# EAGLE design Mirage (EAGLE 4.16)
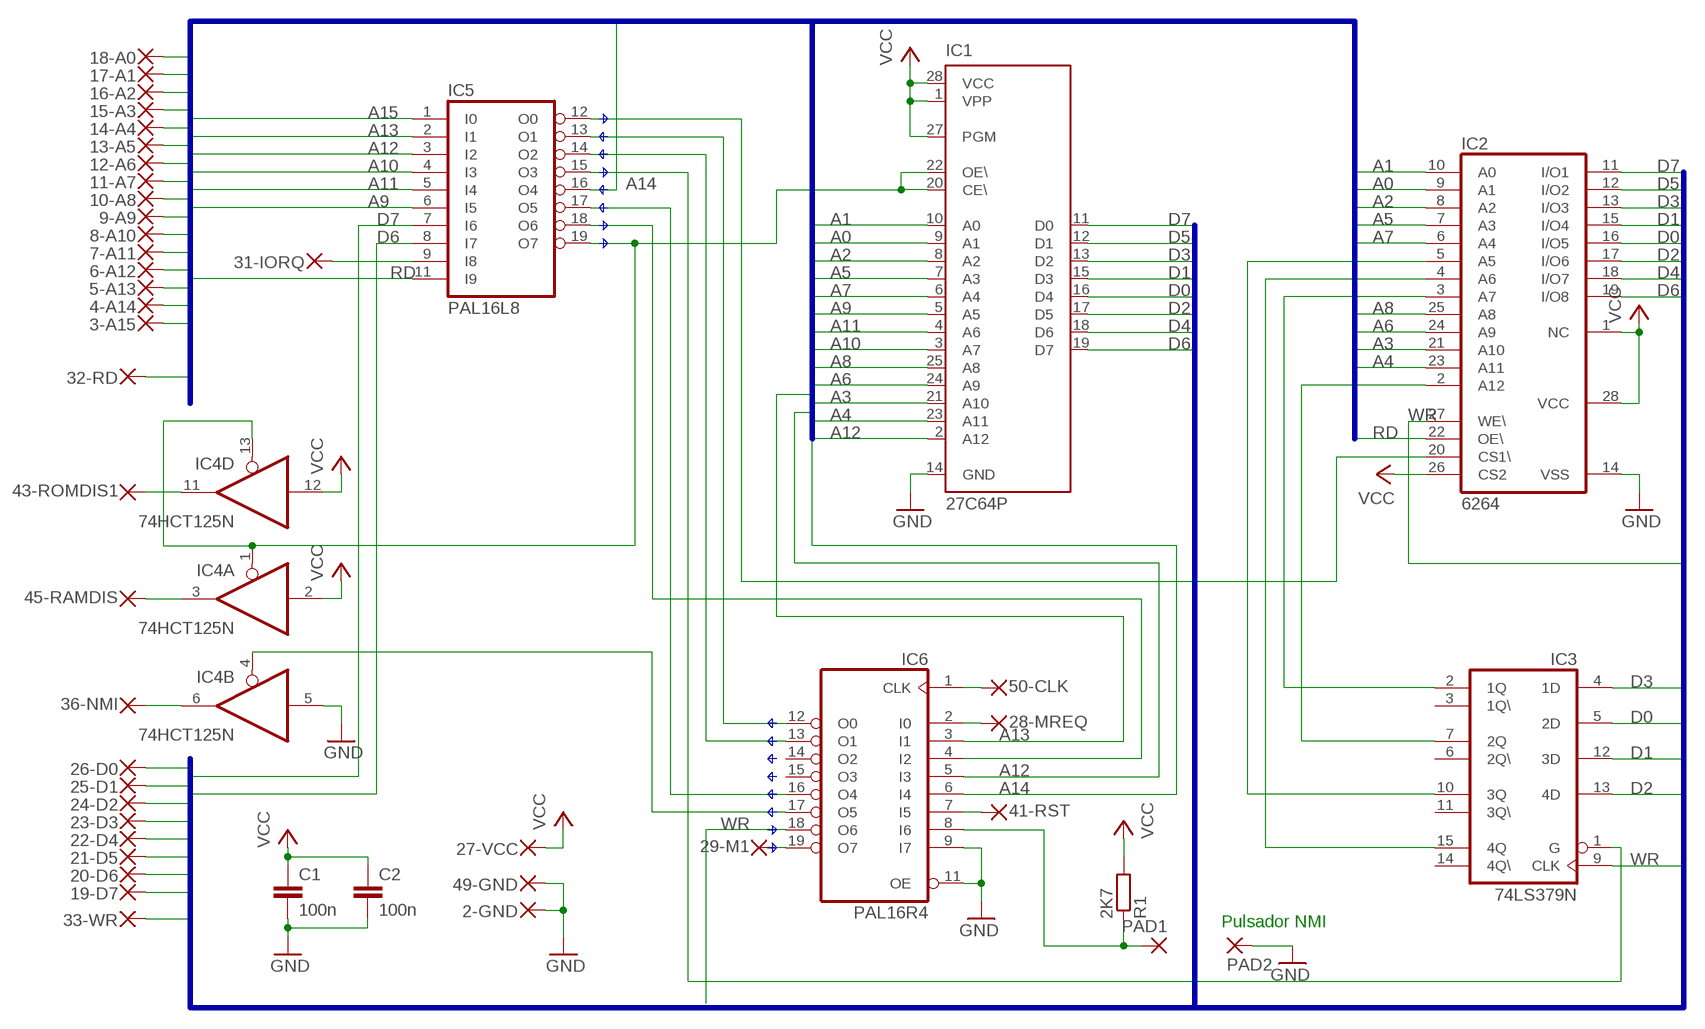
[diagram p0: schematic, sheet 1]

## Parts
2-GND  1,27/0,8  [1,27/0,8]
3-A15  1,27/0,8  [1,27/0,8]
4-A14  1,27/0,8  [1,27/0,8]
5-A13  1,27/0,8  [1,27/0,8]
6-A12  1,27/0,8  [1,27/0,8]
7-A11  1,27/0,8  [1,27/0,8]
8-A10  1,27/0,8  [1,27/0,8]
9-A9  1,27/0,8  [1,27/0,8]
10-A8  1,27/0,8  [1,27/0,8]
11-A7  1,27/0,8  [1,27/0,8]
12-A6  1,27/0,8  [1,27/0,8]
13-A5  1,27/0,8  [1,27/0,8]
14-A4  1,27/0,8  [1,27/0,8]
15-A3  1,27/0,8  [1,27/0,8]
16-A2  1,27/0,8  [1,27/0,8]
17-A1  1,27/0,8  [1,27/0,8]
18-A0  1,27/0,8  [1,27/0,8]
19-D7  1,27/0,8  [1,27/0,8]
20-D6  1,27/0,8  [1,27/0,8]
21-D5  1,27/0,8  [1,27/0,8]
22-D4  1,27/0,8  [1,27/0,8]
23-D3  1,27/0,8  [1,27/0,8]
24-D2  1,27/0,8  [1,27/0,8]
25-D1  1,27/0,8  [1,27/0,8]
26-D0  1,27/0,8  [1,27/0,8]
27-VCC  1,27/0,8  [1,27/0,8]
28-MREQ  1,27/0,8  [1,27/0,8]
29-M1  1,27/0,8  [1,27/0,8]
31-IORQ  1,27/0,8  [1,27/0,8]
32-RD  1,27/0,8  [1,27/0,8]
33-WR  1,27/0,8  [1,27/0,8]
36-NMI  1,27/0,8  [1,27/0,8]
41-RST  1,27/0,8  [1,27/0,8]
43-ROMDIS1  1,27/0,8  [1,27/0,8]
45-RAMDIS  1,27/0,8  [1,27/0,8]
49-GND  1,27/0,8  [1,27/0,8]
50-CLK  1,27/0,8  [1,27/0,8]
C1  100n  C-EU025-024X044  [C025-024X044]
C2  100n  C-EU025-024X044  [C025-024X044]
IC1  27C64P  [DIL28-6]
IC2  6264  6264A  [DIL28-6]
IC3  74LS379N  [DIL16]
IC4  74HCT125N  [DIL14]
IC5  PAL16L8  16L8  [DIL20]
IC6  PAL16R4  16R4  [DIL20]
PAD1  1,6/0,8  [1,6/0,8]
PAD2  1,6/0,8  [1,6/0,8]
R1  2K7  R-EU_0207/10  [0207/10]

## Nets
A0: 18-A0.1(P) IC1.9(A1) IC2.9(A1)
A1: 17-A1.1(P) IC1.10(A0) IC2.10(A0)
A2: 16-A2.1(P) IC1.8(A2) IC2.8(A2)
A3: 15-A3.1(P) IC1.21(A10) IC2.21(A10)
A4: 14-A4.1(P) IC1.23(A11) IC2.23(A11)
A5: 13-A5.1(P) IC1.7(A3) IC2.7(A3)
A6: 12-A6.1(P) IC1.24(A9) IC2.24(A9)
A7: 11-A7.1(P) IC1.6(A4) IC2.6(A4)
A8: 10-A8.1(P) IC1.25(A8) IC2.25(A8)
A9: 9-A9.1(P) IC1.5(A5) IC5.6(I5)
A10: 8-A10.1(P) IC1.3(A7) IC5.4(I3)
A11: 7-A11.1(P) IC1.4(A6) IC5.5(I4)
A12: 6-A12.1(P) IC1.2(A12) IC5.3(I2) IC6.5(I3)
A13: 5-A13.1(P) IC5.2(I1) IC6.3(I1)
A14: 4-A14.1(P) IC5.16(O4) IC6.6(I4)
A15: 3-A15.1(P) IC5.1(I0)
CLK: 50-CLK.1(P) IC6.1(CLK)
D0: 26-D0.1(P) IC1.16(D4) IC2.16(I/O5) IC3.5(2D)
D1: 25-D1.1(P) IC1.15(D3) IC2.15(I/O4) IC3.12(3D)
D2: 24-D2.1(P) IC1.17(D5) IC2.17(I/O6) IC3.13(4D)
D3: 23-D3.1(P) IC1.13(D2) IC2.13(I/O3) IC3.4(1D)
D4: 22-D4.1(P) IC1.18(D6) IC2.18(I/O7)
D5: 21-D5.1(P) IC1.12(D1) IC2.12(I/O2)
D6: 20-D6.1(P) IC1.19(D7) IC2.19(I/O8) IC5.8(I7)
D7: 19-D7.1(P) IC1.11(D0) IC2.11(I/O1) IC5.7(I6)
GND: 2-GND.1(P) 49-GND.1(P) C1.2 C2.2 IC1.14(GND) IC2.14(VSS) IC4.5(B:I) IC6.9(I7) IC6.11(OE) PAD2.1(P)
IORQ: 31-IORQ.1(P) IC5.9(I8)
M1: 29-M1.1(P) IC6.19(O7)
MREQ: 28-MREQ.1(P) IC6.2(I0)
N$1: IC5.13(O1) IC6.12(O0)
N$2: IC6.8(I6) PAD1.1(P) R1.1
N$3: IC5.14(O2) IC6.13(O1)
N$4: IC2.5(A5) IC3.10(3Q)
N$5: IC2.4(A6) IC3.15(4Q)
N$8: IC5.18(O6) IC6.4(I2)
N$9: IC5.17(O5) IC6.16(O4)
N$10: IC4.4(B:OE) IC6.17(O5)
N$11: 36-NMI.1(P) IC4.6(B:O)
N$12: IC3.1(G) IC5.15(O3)
N$13: IC2.2(A12) IC3.7(2Q)
N$14: IC2.3(A7) IC3.2(1Q)
N$17: 45-RAMDIS.1(P) IC4.3(A:O)
N$18: 43-ROMDIS1.1(P) IC4.11(D:O)
RAMCS: IC2.20(CS1\) IC5.12(O0)
RD: 32-RD.1(P) IC2.22(OE\) IC5.11(I9)
RST: 41-RST.1(P) IC6.7(I5)
SALIDA19: IC1.20(CE\) IC1.22(OE\) IC4.1(A:OE) IC4.13(D:OE) IC5.19(O7)
VCC: 27-VCC.1(P) C1.1 C2.1 IC1.1(VPP) IC1.27(PGM) IC1.28(VCC) IC2.1(NC) IC2.26(CS2) IC2.28(VCC) IC4.2(A:I) IC4.12(D:I) R1.2
WR: 33-WR.1(P) IC2.27(WE\) IC3.9(CLK) IC6.18(O6)
Unconnected: IC1.26(NC) IC3.3(1Q\) IC3.6(2Q\) IC3.11(3Q\) IC3.14(4Q\) IC4.8(C:O) IC4.9(C:I) IC4.10(C:OE) IC6.14(O2) IC6.15(O3)

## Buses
A[0..15],RD
D[0..7],WR
B$1
B$3
B$4
B$2
B$5
B$6
B$7
B$8
B$9
B$10
B$11
B$12
B$13
B$14
B$15
B$16

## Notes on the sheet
- Pulsador NMI

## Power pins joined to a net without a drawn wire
GND: IC3.8(GND) IC4.7(P:GND) IC5.10(GND) IC6.10(GND)
VCC: IC3.16(VCC) IC4.14(P:VCC) IC5.20(VCC) IC6.20(VCC)

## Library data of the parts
2-GND 3-A15 4-A14 5-A13 6-A12 7-A11 8-A10 9-A9 10-A8 11-A7 12-A6 13-A5 14-A4 15-A3 16-A2 17-A1 18-A0 19-D7 20-D6 21-D5 22-D4 23-D3 24-D2 25-D1 26-D0 27-VCC 28-MREQ 29-M1 31-IORQ 32-RD 33-WR 36-NMI 41-RST 43-ROMDIS1 45-RAMDIS 49-GND 50-CLK = wirepad2:1,27/0,8: Pad 1,27/0,8
C1 C2 = rcl:C-EU: CAPACITOR, European symbol
IC1 = microchip:27*64: CMOS EPROM 64 K (8 K x 8), low voltage
IC2 = memory-hitachi:6264A: MEMORY
IC3 = 74xx-eu:74*379: Quad D type FLIP FLOP, enable
IC4 = 74xx-eu:74*125: Quad bus BUFFER, 3-state
IC5 = pal:16L8: PAL
IC6 = pal:16R4: PAL
PAD1 PAD2 = wirepad:1,6/0,8: THROUGH-HOLE PAD
R1 = rcl:R-EU_: RESISTOR, European symbol

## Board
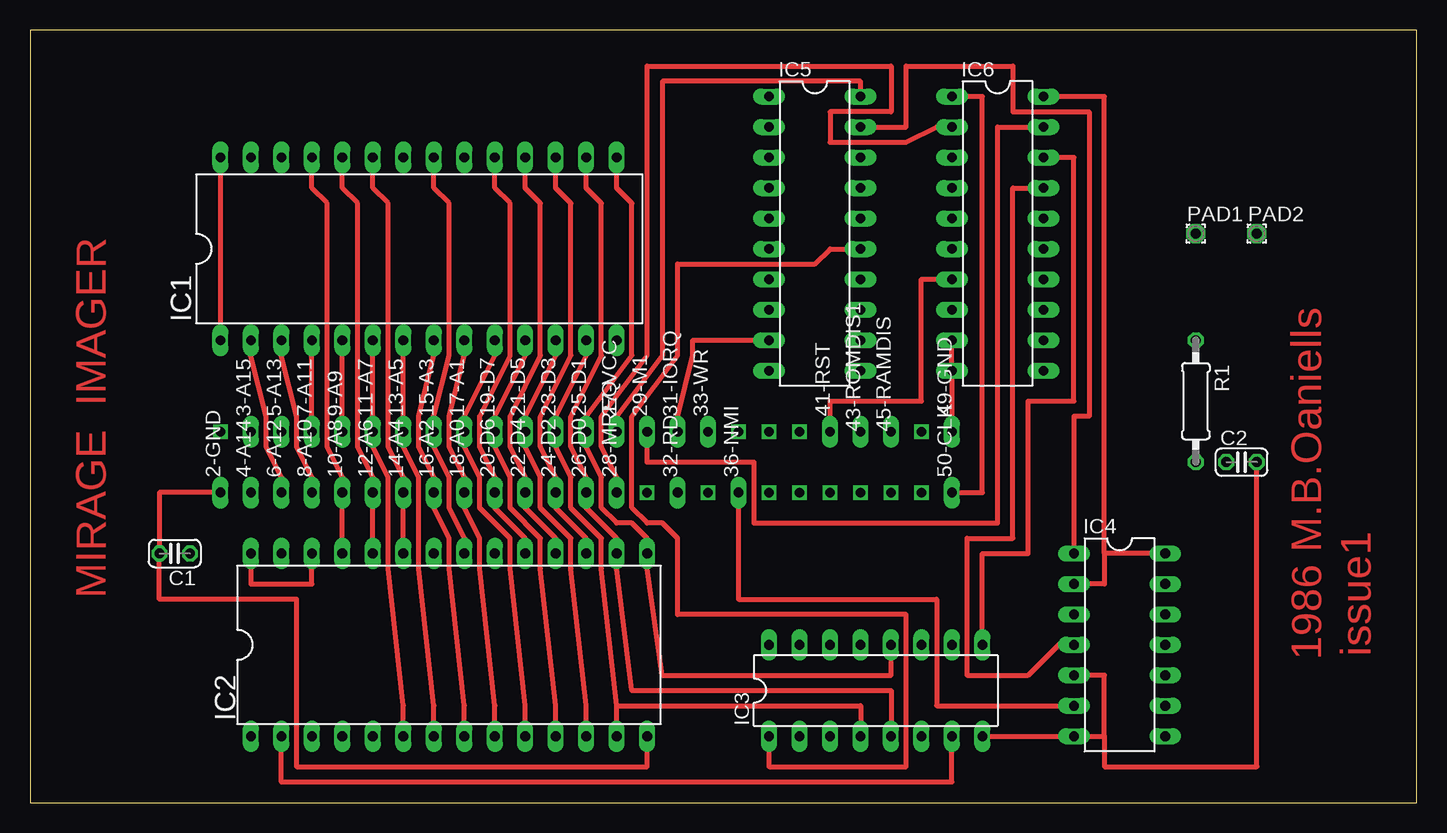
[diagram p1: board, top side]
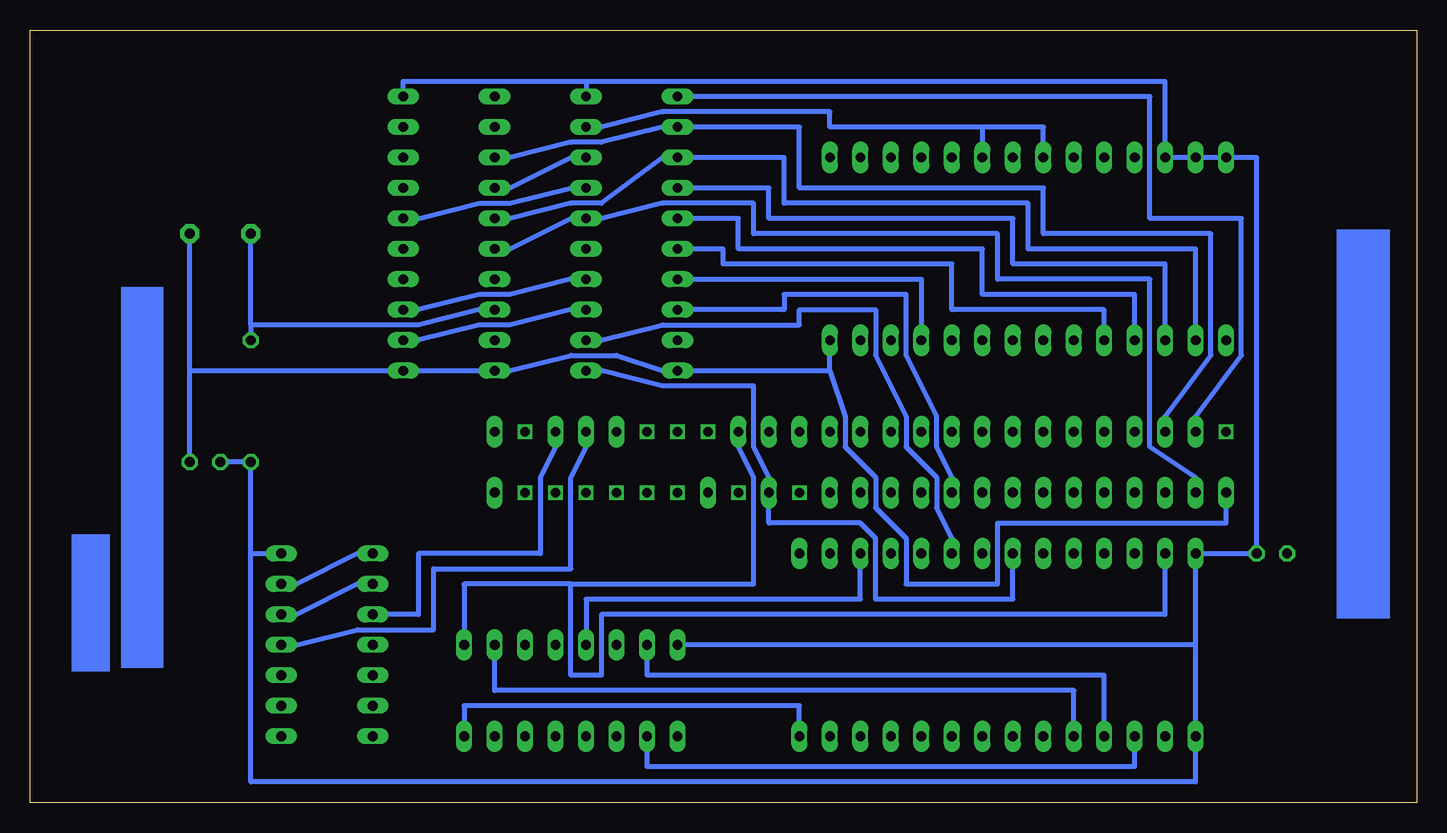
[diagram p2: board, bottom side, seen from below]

Size 115.55 x 64.44 mm. Coordinates in mm from the lower left corner, seen from the top.
Outline: 0,0 115.55,0 115.55,64.44 0,64.44 0,0
Copper layers (1*16): Top 0.035mm / dielectric 1.5mm / Bottom 0.035mm
Design rules "default": minimum track width 10mil, minimum drill 24mil, track to track 8mil, track to pad 8mil, pad to pad 8mil, via to via 8mil, smd to smd 8mil, copper to edge 40mil, drill to drill 8mil, minimum pad ring 10mil, minimum via ring 8mil, stop-mask expansion 4mil, vias tented up to drill 0mil, thermal gap 10mil

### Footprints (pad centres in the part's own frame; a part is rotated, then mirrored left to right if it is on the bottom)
1,27/0,8 = drill 0.813 long: 1 -1.27,1.27
C025-024X044 = drill 0.813 octagon: 1 -1.27,0; 2 1.27,0
DIL28-6 = drill 0.813 long: 1 -16.51,-7.62; 2 -13.97,-7.62; 3 -11.43,-7.62; 4 -8.89,-7.62; 5 -6.35,-7.62; 6 -3.81,-7.62; 7 -1.27,-7.62; 8 1.27,-7.62; 9 3.81,-7.62; 10 6.35,-7.62; 11 8.89,-7.62; 12 11.43,-7.62; 13 13.97,-7.62; 14 16.51,-7.62; 15 16.51,7.62; 16 13.97,7.62; 17 11.43,7.62; 18 8.89,7.62; 19 6.35,7.62; 20 3.81,7.62; 21 1.27,7.62; 22 -1.27,7.62; 23 -3.81,7.62; 24 -6.35,7.62; 25 -8.89,7.62; 26 -11.43,7.62; 27 -13.97,7.62; 28 -16.51,7.62
DIL16 = drill 0.813 long: 1 -8.89,-3.81; 2 -6.35,-3.81; 3 -3.81,-3.81; 4 -1.27,-3.81; 5 1.27,-3.81; 6 3.81,-3.81; 7 6.35,-3.81; 8 8.89,-3.81; 9 8.89,3.81; 10 6.35,3.81; 11 3.81,3.81; 12 1.27,3.81; 13 -1.27,3.81; 14 -3.81,3.81; 15 -6.35,3.81; 16 -8.89,3.81
DIL14 = drill 0.813 long: 1 -7.62,-3.81; 2 -5.08,-3.81; 3 -2.54,-3.81; 4 0,-3.81; 5 2.54,-3.81; 6 5.08,-3.81; 7 7.62,-3.81; 8 7.62,3.81; 9 5.08,3.81; 10 2.54,3.81; 11 0,3.81; 12 -2.54,3.81; 13 -5.08,3.81; 14 -7.62,3.81
DIL20 = drill 0.813 long: 1 -11.43,-3.81; 2 -8.89,-3.81; 3 -6.35,-3.81; 4 -3.81,-3.81; 5 -1.27,-3.81; 6 1.27,-3.81; 7 3.81,-3.81; 8 6.35,-3.81; 9 8.89,-3.81; 10 11.43,-3.81; 11 11.43,3.81; 12 8.89,3.81; 13 6.35,3.81; 14 3.81,3.81; 15 1.27,3.81; 16 -1.27,3.81; 17 -3.81,3.81; 18 -6.35,3.81; 19 -8.89,3.81; 20 -11.43,3.81
1,6/0,8 = drill 0.813 pad 1.6 octagon: 1 0,0
0207/10 = drill 0.813 octagon: 1 -5.08,0; 2 5.08,0

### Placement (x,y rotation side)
2-GND  17.14,24.6 0 top
3-A15  19.68,29.68 0 top
4-A14  19.68,24.6 0 top
5-A13  22.22,29.68 0 top
6-A12  22.22,24.6 0 top
7-A11  24.76,29.68 0 top
8-A10  24.76,24.6 0 top
9-A9  27.3,29.68 0 top
10-A8  27.3,24.6 0 top
11-A7  29.84,29.68 0 top
12-A6  29.84,24.6 0 top
13-A5  32.38,29.68 0 top
14-A4  32.38,24.6 0 top
15-A3  34.92,29.68 0 top
16-A2  34.92,24.6 0 top
17-A1  37.46,29.68 0 top
18-A0  37.46,24.6 0 top
19-D7  40,29.68 0 top
20-D6  40,24.6 0 top
21-D5  42.54,29.68 0 top
22-D4  42.54,24.6 0 top
23-D3  45.08,29.68 0 top
24-D2  45.08,24.6 0 top
25-D1  47.62,29.68 0 top
26-D0  47.62,24.6 0 top
27-VCC  50.16,29.68 0 top
28-MREQ  50.16,24.6 0 top
29-M1  52.7,29.68 0 top
31-IORQ  55.24,29.68 0 top
32-RD  55.24,24.6 0 top
33-WR  57.78,29.68 0 top
36-NMI  60.32,24.6 0 top
41-RST  67.94,29.68 0 top
43-ROMDIS1  70.48,29.68 0 top
45-RAMDIS  73.02,29.68 0 top
49-GND  78.1,29.68 0 top
50-CLK  78.1,24.6 0 top
C1  12.06,20.79 180 top
C2  100.96,28.41 0 top
IC1  32.38,46.19 0 top
IC2  34.92,13.17 0 top
IC3  70.48,9.36 0 top
IC4  90.8,13.17 270 top
IC5  65.4,47.46 270 top
IC6  80.64,47.46 270 top
PAD1  97.15,47.46 0 top
PAD2  102.23,47.46 0 top
R1  97.15,33.49 270 top

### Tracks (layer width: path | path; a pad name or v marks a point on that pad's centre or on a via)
A0
  Top 0.406: IC1.9 36.19,37.3 34.92,32.22 34.92,29.68 36.19,27.14 18-A0.1 36.19,24.6 37.46,22.06 37.46,19.52 38.73,8.09 IC2.9
A1
  Top 0.406: IC1.10 38.73,37.3 36.19,32.22 17-A1.1 36.19,29.68 37.46,27.14 37.46,24.6 40,22.06 40,19.52 41.27,8.09 IC2.10
A2
  Top 0.406: IC1.8 33.65,37.3 32.38,32.22 32.38,29.68 33.65,27.14 16-A2.1 33.65,24.6 34.92,22.06 34.92,19.52 36.19,8.09 IC2.8
A3
  Top 0.406: IC1.21 33.65,51.27 34.92,50 34.92,37.3 33.65,32.22 15-A3.1 33.65,29.68 34.92,27.14 34.92,24.6 36.19,22.06 IC2.21
A4
  Top 0.406: IC1.23 28.57,51.27 29.84,50 29.84,29.68 31.11,27.14 14-A4.1 IC2.23
A5
  Top 0.406: IC1.7 13-A5.1 31.11,29.68 32.38,27.14 32.38,19.52 33.65,8.09 IC2.7
A6
  Top 0.406: IC1.24 26.03,51.27 27.3,50 27.3,29.68 28.57,27.14 12-A6.1 IC2.24
A7
  Top 0.406: IC1.6 11-A7.1 28.57,29.68 29.84,27.14 29.84,19.52 31.11,8.09 IC2.6
A8
  Top 0.406: IC1.25 23.49,51.27 24.76,50 24.76,29.68 26.03,27.14 10-A8.1 IC2.25
A9
  Top 0.406: 9-A9.1 IC1.5
  Bottom 0.406: IC1.5 26.03,41.11 38.73,41.11 38.73,44.92 57.78,44.92 57.78,46.19 IC5.6
A10
  Top 0.406: IC1.3 20.95,37.3 22.22,32.22 22.22,29.68 23.49,27.14 8-A10.1
  Bottom 0.406: IC1.3 20.95,44.92 33.65,44.92 33.65,48.73 53.97,48.73 53.97,51.27 IC5.4
A11
  Top 0.406: 7-A11.1 IC1.4
  Bottom 0.406: IC5.5 56.51,48.73 56.51,46.19 36.19,46.19 36.19,42.38 23.49,42.38 IC1.4
A12
  Top 0.406: IC1.2 18.41,37.3 19.68,32.22 19.68,29.68 20.95,27.14 6-A12.1
  Bottom 0.406: IC1.2 18.41,46.19 32.38,46.19 32.38,50 52.7,50 52.7,53.81 IC5.3 62.86,53.81 67.94,50 70.48,50 75.56,48.73 IC6.5
A13
  Bottom 0.406: 5-A13.1 20.95,32.22 17.14,37.3 17.14,47.46 31.11,47.46 31.11,51.27 51.43,51.27 51.43,56.35 IC5.2 62.86,56.35 67.94,55.08 70.48,55.08 75.56,53.81 IC6.3
A14
  Bottom 0.406: 4-A14.1 18.41,27.14 22.22,29.68 22.22,43.65 34.92,43.65 34.92,47.46 55.24,47.46 55.24,50 62.86,50 67.94,48.73 IC5.16 70.48,48.73 75.56,46.19 IC6.6
A15
  Bottom 0.406: 3-A15.1 18.41,32.22 14.6,37.3 14.6,48.73 22.22,48.73 22.22,58.89 IC5.1
CLK
  Top 0.406: 50-CLK.1 79.37,25.87 79.37,58.89 IC6.1
D0
  Top 0.406: IC1.16 46.35,51.27 47.62,50 47.62,37.3 45.08,32.22 45.08,29.68 46.35,27.14 26-D0.1 46.35,24.6 48.89,22.06 IC2.16 48.89,19.52 50.16,9.36 71.75,9.36 IC3.5
D1
  Top 0.406: IC1.15 48.89,51.27 50.16,50 50.16,37.3 46.35,32.22 25-D1.1 46.35,29.68 47.62,27.14 47.62,24.6 48.89,23.33 50.16,23.33 51.43,22.06 IC2.15 51.43,19.52 52.7,10.63 71.75,10.63 IC3.12
D2
  Top 0.406: IC2.17 46.35,22.06 43.81,24.6 24-D2.1 43.81,27.14 42.54,29.68 42.54,32.22 45.08,37.3 45.08,50 43.81,51.27 IC1.17
  Bottom 0.406: IC2.17 46.35,16.98 69.21,16.98 IC3.13
D3
  Top 0.406: IC3.4 69.21,8.09 48.89,8.09 | IC2.13 48.89,8.09 | IC1.13 46.35,37.3 43.81,32.22 23-D3.1 43.81,29.68 45.08,27.14 45.08,24.6 47.62,22.06 47.62,19.52 48.89,8.09
D4
  Top 0.406: IC2.18 43.81,22.06 41.27,24.6 22-D4.1 41.27,27.14 40,29.68 40,32.22 42.54,37.3 42.54,50 41.27,51.27 IC1.18
D5
  Top 0.406: IC2.12 46.35,8.09 45.08,19.52 45.08,22.06 42.54,24.6 42.54,27.14 41.27,29.68 21-D5.1 41.27,32.22 43.81,37.3 IC1.12
D6
  Top 0.406: IC2.19 41.27,22.06 38.73,24.6 20-D6.1 38.73,27.14 37.46,29.68 37.46,32.22 40,37.3 40,50 38.73,51.27 IC1.19
  Bottom 0.406: IC5.8 52.7,41.11 52.7,42.38 42.54,42.38 42.54,37.3 40,32.22 40,29.68 38.73,27.14 20-D6.1
D7
  Top 0.406: IC2.11 43.81,8.09 42.54,19.52 42.54,22.06 40,24.6 40,27.14 38.73,29.68 19-D7.1 38.73,32.22 41.27,37.3 IC1.11
  Bottom 0.406: IC5.7 41.27,43.65 IC1.11
GND
  Top 0.406: C2.2 102.23,3.01 89.53,3.01 89.53,5.55 | IC4.5 89.53,10.63 89.53,5.55 | 89.53,5.55 IC4.7 IC3.8 | IC2.14 51.43,3.01 22.22,3.01 22.22,16.98 10.79,16.98 C1.2 10.79,25.87 2-GND.1 | 49-GND.1 IC6.10 IC6.9
  Bottom 0.406: 48.89,36.03 IC1.14 | 48.89,36.03 IC5.10 62.86,36.03 66.67,37.3 70.48,37.3 75.56,36.03 IC6.10 IC6.11 102.23,36.03 | 102.23,36.03 PAD2.1 | C2.2 102.23,36.03 | IC3.8 79.37,8.09 51.43,8.09 IC2.14 | 2-GND.1 15.87,23.33 34.92,23.33 34.92,18.25 42.54,18.25 42.54,22.06 45.08,24.6 45.08,27.14 47.62,29.68 47.62,32.22 48.89,36.03
IORQ
  Top 0.406: IC5.9 55.24,38.57 55.24,37.3 53.97,32.22 31-IORQ.1
M1
  Top 0.406: 29-M1.1 51.43,28.41 60.32,28.41 60.32,23.33 80.64,23.33 80.64,56.35 IC6.19
MREQ
  Top 0.406: IC6.2 75.56,56.35 73.02,55.08 66.67,55.08 66.67,57.62 71.75,57.62 71.75,61.43 51.43,61.43 51.43,37.3 47.62,32.22 47.62,29.68 48.89,27.14 28-MREQ.1
N$1
  Bottom 0.406: IC5.13 70.48,41.11 75.56,39.84 78.1,39.84 83.18,38.57 IC6.12
N$2
  Bottom 0.406: 97.15,39.84 R1.1 | 97.15,39.84 PAD1.1 | IC6.8 78.1,41.11 83.18,39.84 97.15,39.84
N$3
  Bottom 0.406: IC5.14 70.48,43.65 75.56,42.38 78.1,42.38 83.18,41.11 IC6.13
N$4
  Bottom 0.406: IC3.10 76.83,9.36 28.57,9.36 IC2.5
N$5
  Bottom 0.406: IC2.4 26.03,10.63 64.13,10.63 IC3.15
N$6  (via drill 0.8)
  other vias: 56.51,25.87
N$7  (via drill 0.8)
  other vias: 59.05,30.95
N$8
  Bottom 0.406: IC5.18 70.48,53.81 75.56,51.27 IC6.4
N$9
  Bottom 0.406: IC6.16 83.18,48.73 78.1,50 75.56,50 70.48,51.27 IC5.17
N$10
  Top 0.406: IC6.17 81.91,51.27 81.91,22.06 78.1,22.06 78.1,10.63 83.18,10.63 85.72,13.17 IC4.4
N$11
  Top 0.406: 36-NMI.1 59.05,16.98 75.56,16.98 75.56,8.09 IC4.6
N$12
  Top 0.406: IC5.15 66.67,46.19 65.4,44.92 53.97,44.92 53.97,37.3 50.16,32.22 50.16,24.6 51.43,23.33 52.7,23.33 53.97,22.06 53.97,15.71 73.02,15.71 73.02,3.01 61.59,3.01 IC3.1
N$13
  Top 0.406: IC3.7 76.83,1.74 20.95,1.74 IC2.2
N$14
  Bottom 0.406: IC2.3 23.49,3.01 64.13,3.01 IC3.2
N$15  (via drill 0.8)
  other vias: 61.59,30.95
N$16  (via drill 0.8)
  other vias: 64.13,30.95
N$17
  Bottom 0.406: 45-RAMDIS.1 71.75,29.68 73.02,27.14 73.02,20.79 83.18,20.79 83.18,15.71 IC4.3
N$18
  Bottom 0.406: IC4.11 93.34,13.17 88.26,14.44 81.91,14.44 81.91,19.52 70.48,19.52 70.48,27.14 69.21,29.68 43-ROMDIS1.1
N$19  (via drill 0.8)
  other vias: 64.13,25.87
N$20  (via drill 0.8)
  other vias: 61.59,25.87
N$21  (via drill 0.8)
  other vias: 66.67,25.87
N$22  (via drill 0.8)
  other vias: 69.21,25.87
N$23  (via drill 0.8)
  other vias: 71.75,25.87
N$24  (via drill 0.8)
  other vias: 74.29,25.87
N$25  (via drill 0.8)
  other vias: 74.29,30.95
N$26  (via drill 0.8)
  other vias: 51.43,25.87
N$27  (via drill 0.8)
  other vias: 15.87,30.95
RAMCS
  Bottom 0.406: IC5.12 67.94,38.57 62.86,39.84 51.43,39.84 51.43,41.11 45.08,41.11 45.08,37.3 42.54,32.22 42.54,29.68 40,27.14 40,24.6 38.73,22.06 IC2.20
RD
  Bottom 0.406: IC2.22 33.65,16.98 45.08,16.98 45.08,22.06 46.35,23.33 53.97,23.33 32-RD.1 53.97,27.14 55.24,29.68 55.24,34.76 62.86,34.76 67.94,36.03 IC5.11
RST
  Top 0.406: 41-RST.1 66.67,33.49 74.29,33.49 74.29,43.65 IC6.7
SALIDA19
  Top 0.406: IC4.1 86.99,32.22 88.26,32.22 88.26,57.62 81.91,57.62 81.91,61.43 73.02,61.43 73.02,56.35 IC5.19
  Bottom 0.406: IC4.1 88.26,20.79 93.34,18.25 IC4.13 | IC1.22 31.11,56.35 36.19,56.35 | 36.19,56.35 IC1.20 | IC5.19 67.94,56.35 62.86,57.62 48.89,57.62 48.89,56.35 36.19,56.35
VCC
  Top 0.406: IC6.20 89.53,58.89 89.53,20.79 | IC4.14 89.53,20.79 | IC4.2 89.53,18.25 89.53,20.79 | IC5.20 69.21,60.16 52.7,60.16 52.7,37.3 48.89,32.22 27-VCC.1 | IC1.28 IC1.1 | IC2.28 18.41,18.25 23.49,18.25 IC2.26
  Bottom 0.406: 69.21,60.16 20.95,60.16 20.95,53.81 IC1.27 IC1.28 13.33,53.81 C1.1 IC2.28 18.41,13.17 | 69.21,60.16 84.45,60.16 IC6.20 | 18.41,13.17 IC2.1 18.41,1.74 97.15,1.74 97.15,20.79 | 97.15,20.79 IC4.14 | 18.41,13.17 IC3.16 | 69.21,60.16 IC5.20 | 97.15,20.79 R1.2 C2.1 | IC4.12 93.34,15.71 88.26,18.25 IC4.2
WR
  Top 0.406: IC6.18 86.99,53.81 86.99,33.49 83.18,33.49 83.18,20.79 79.37,20.79 IC3.9
  Bottom 0.406: 70.48,18.25 70.48,10.63 67.94,10.63 67.94,15.71 20.95,15.71 IC2.27 | 70.48,18.25 79.37,18.25 IC3.9 | 33-WR.1 56.51,29.68 55.24,27.14 55.24,18.25 70.48,18.25
(copper drawn outside any net)
  shapes: Bottom area x3

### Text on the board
Top: MIRAGE IMAGER | issue1 | 1986 M.B.Oaniells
